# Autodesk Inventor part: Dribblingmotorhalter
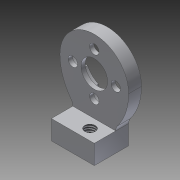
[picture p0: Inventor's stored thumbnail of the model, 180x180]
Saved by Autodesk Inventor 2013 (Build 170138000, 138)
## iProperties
Created: 2012-07
Part Number: Dribblingmotorhalter
Material: Aluminium 6061
Document SubType Name: Modeling
Designer: rYan
Density: 2.71 g/cm^3
Mass: 2.08532 g
Surface Area: 9.75871 cm^2
Volume: 0.769491 cm^3
Author: rYan
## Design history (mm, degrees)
sketch "Skizze1"
  geometry: L1 (0, -4.3)-(0, 25.8) reference; L2 (-8.139, 21.5)-(7.861, 21.5); L3 (-8, 13.5)-(8, 13.5); L4 (-5, 4.5)-(-5, 0); L5 (-5, 0)-(5, 0); L6 (5, 0)-(5, 4.5); L7 (-12.086, 0)-(12.086, 0) reference; A1 r 8 centre (0, 13.5) between (8, 13.5) and (-8, 13.5); A2 r 13 centre (5, 13.5) between (-8, 13.5) and (-5.4, 5.7); A3 r 13 centre (-5, 13.5) between (5.4, 5.7) and (8, 13.5); A4 r 2 centre (-7, 4.5) between (-5, 4.5) and (-5.4, 5.7); A5 r 2 centre (7, 4.5) between (5.4, 5.7) and (5, 4.5); 1 further point
  constraints: 10 end point, 10 point on circle, 6 tangent, 5 centre point, 2 parallel, 2 perpendicular, 1 collinear, 1 midpoint, 1 symmetric about line, 2 other
  dimensions: "d43" = 8 radius of A1; "d45" = 21.5 distance between parallel lines of L2 L5; "d46" = 4.5 distance of L4.start L4.end; "d48" = 10 distance of L4.end L5.end; "d77" = 2 radius of A4; "d78" = 2 radius of A5
extrude "Extrusion1" new body sketch "Skizze1" distance "d3" = 3; taper "d4" = 0 deg
sketch "Skizze2"
  geometry: L1 (0, 25.8)-(0, -4.3) reference; L2 (-5, 0)-(-5, 4.5) reference; L3 (5, 0)-(-5, 0) reference; L4 (5, 4.5)-(5, 0) reference; L5 (-5, 4.5)-(5, 4.5); L6 (5, 4.5)-(5, 0); L7 (5, 0)-(-5, 0); L8 (-5, 0)-(-5, 4.5); 1 further point
  constraints: 8 end point, 2 parallel, 1 horizontal, 1 perpendicular
extrude "Extrusion2" join sketch "Skizze2" distance "d7" = 5; taper "d8" = 0 deg
sketch "Skizze13"
  geometry: A1 r 8 centre (0, -13.5) between (-8, -13.5) and (8, -13.5) reference; 2 further points
  constraints: 1 coincident
hole "Bohrung8" sketch "Skizze13" at (0, -13.5) diameter "d101" = 6.2; stored, may be unused: countersink angle "d105" = 90 deg, drill point angle "d107" = 118 deg; dims "d102" = 6, "d103" = 10, "d104" = 2, "d106" = 3
sketch "Skizze5" dims "d19" = 10
  geometry: L1 (0, 4.3)-(0, -25.8) reference; C1 r 3.1 at (0, -13.5) reference; 3 further points
  constraints: 1 coincident, 1 point on line, 1 vertical alignment, 2 other
hole "Bohrung2" sketch "Skizze5" at (0, -18.5) diameter "d21" = 2.2; stored, may be unused: countersink angle "d25" = 90 deg, drill point angle "d27" = 118 deg; dims "d22" = 6, "d23" = 4.2, "d24" = 2, "d26" = 8
sketch "Skizze11"
  geometry: L1 (10, -8)-(10, 0) reference; L2 (0, 0)-(10, 0) reference; L3 (0, -8)-(0, 0) reference; L4 (10, -8)-(0, -8) reference; 2 further points
  dimensions: "d82" = 3.5 distance from line of point (3.5, -5.5) L3; "d111" = 2.5 distance from line of L4 point (3.5, -5.5)
hole "Bohrung6" sketch "Skizze11" at (3.5, -5.5) diameter "d83" = 2.459; stored, may be unused: countersink angle "d87" = 90 deg, drill point angle "d89" = 118 deg; dims "d84" = 3, "d85" = 4, "d86" = 2, "d88" = 4
sketch "Skizze12"
  geometry: L1 (10, -8)-(10, 0) reference; L2 (0, 0)-(10, 0) reference; L3 (0, -8)-(0, 0) reference; L4 (10, -8)-(0, -8) reference; L5 (0, -4)-(10, -4); L6 (8.2, -2)-(8.2, -6); C1 r 1.23 at (3.5, -5.5) reference; 1 further point
  constraints: 4 end point, 2 midpoint, 1 perpendicular, 1 symmetric about line
  dimensions: "d90" = 4 distance of L6.start L6.end; "d100" = 1.8 distance between parallel lines of L1 L6
hole "Bohrung7" sketch "Skizze12" at (8.2, -2), (8.2, -6) diameter "d93" = 2; stored, may be unused: countersink angle "d97" = 90 deg, drill point angle "d99" = 118 deg; dims "d94" = 6, "d95" = 4, "d96" = 2, "d98" = 3
pattern_circular "Runde Anordnung2" dims angle "d109" = 360 deg
node "Volumenkörper1"
node "Projizierte Kontur1"
node "Projizierte Kontur2"
